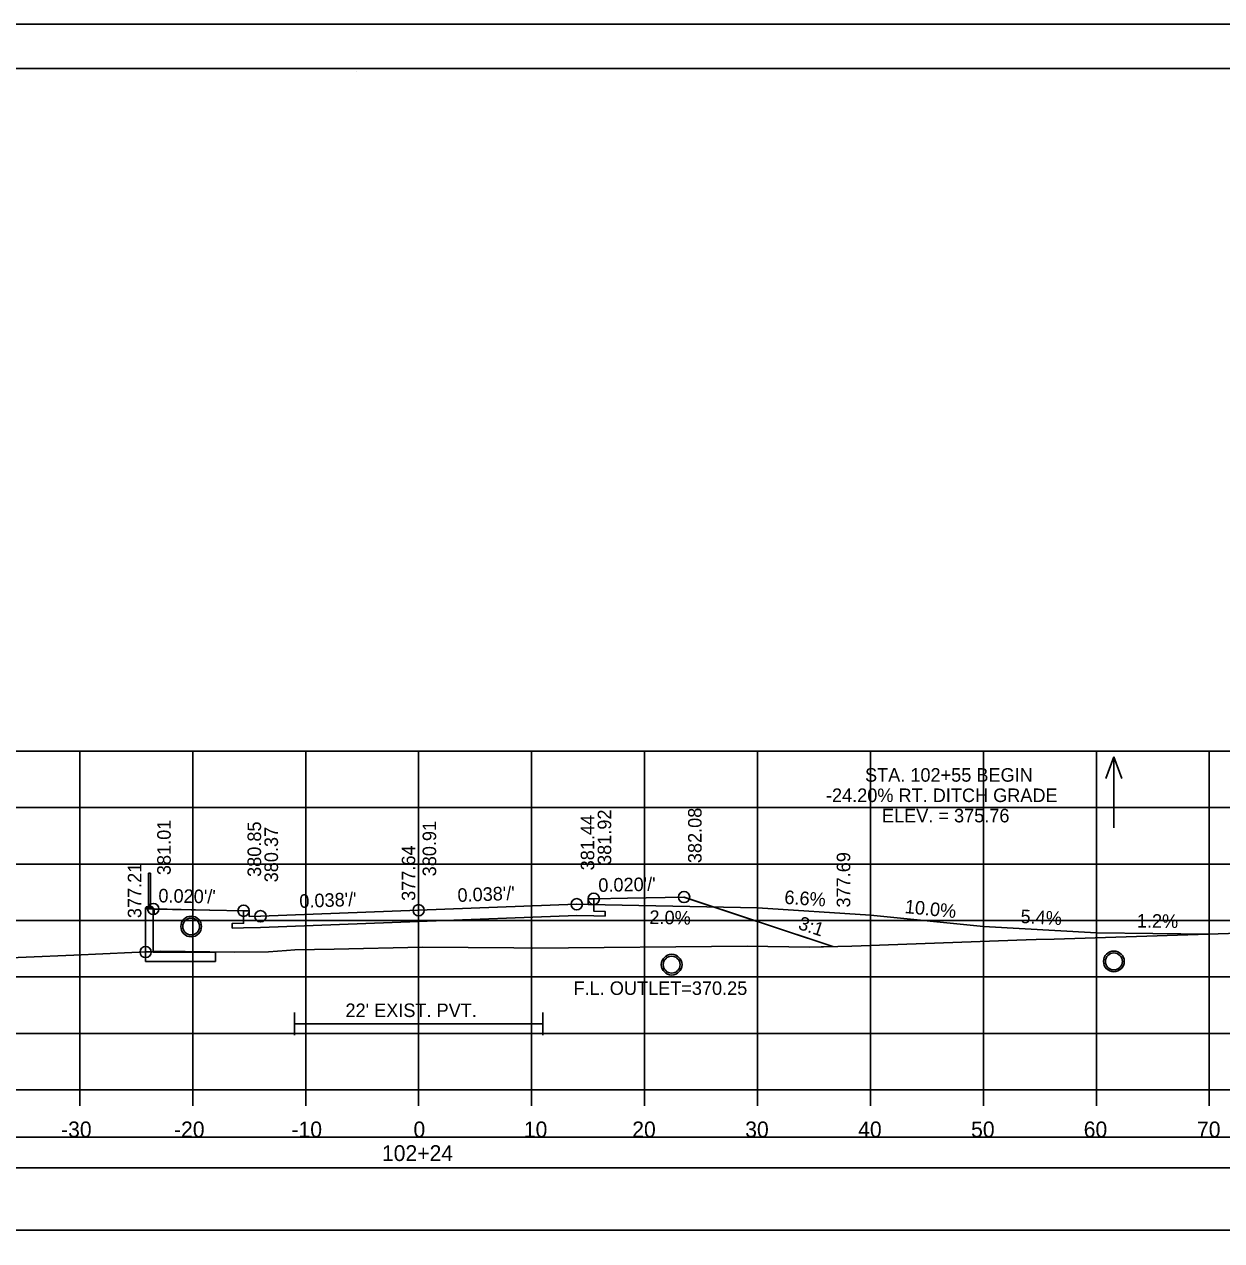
# Model space of a CAD drawing. Extents: x -37291014 to -37290680, y -936053 to -933067.
# Drawn here: x -37290878 to -37290772, y -935521 to -935413.3 of the extents above; entities that cross this region are included whole.
import ezdxf

# ---------------------------------------------------------------- set-up
doc = ezdxf.new("R2010")
doc.units = 0
for name, color, linetype in [('Default', 7, 'Continuous'), ('R_Alt Surface', 7, 'Continuous'), ('R_Axis', 7, 'Continuous'), ('R_Axis Annot', 7, 'Continuous'), ('R_Border', 7, 'Continuous'), ('R_Contours', 7, 'Continuous'), ('R_Drive', 7, 'Continuous'), ('R_Exist Surface', 7, 'Continuous'), ('R_Fin Surface', 7, 'Continuous'), ('R_Grid', 7, 'Continuous'), ('R_No Plot', 7, 'Continuous'), ('R_Water', 7, 'Continuous'), ('R_Water Annot', 7, 'Continuous'), ('R_Xsect Elev', 7, 'Continuous'), ('R_Xsect Slope', 7, 'Continuous')]:
    doc.layers.add(name, color=color, linetype=linetype)

msp = doc.modelspace()

# ---------------------------------------------------------------- linework, layer by layer
at = {"layer": 'Default'}
for p, q in [((-37290867.02, -935491.45), (-37290867.02, -935488.45)), ((-37290867.02, -935488.45), (-37290866.85, -935488.45)), ((-37290866.85, -935488.45), (-37290866.85, -935491.45)), ((-37290867.21, -935491.47), (-37290867.27, -935491.53)), ((-37290867.27, -935491.53), (-37290867.27, -935496.28)), ((-37290866.66, -935491.45), (-37290867.21, -935491.45)), ((-37290867.21, -935491.45), (-37290867.21, -935491.47)), ((-37290866.66, -935491.47), (-37290867.21, -935491.47)), ((-37290866.66, -935491.47), (-37290866.66, -935491.45)), ((-37290866.6, -935491.53), (-37290866.66, -935491.47)), ((-37290866.6, -935495.44), (-37290866.6, -935491.53)), ((-37290861.1, -935496.28), (-37290867.27, -935496.28)), ((-37290861.1, -935495.44), (-37290866.6, -935495.44)), ((-37290861.1, -935496.28), (-37290861.1, -935495.44))]:
    msp.add_line(p, q, dxfattribs=at)
msp.add_lwpolyline([(-37290866.52, -935492.13), (-37290866.6, -935492.13), (-37290866.6, -935491.63), (-37290866.52, -935491.63), (-37290866.52, -935492.13)], dxfattribs=at)
for points in [[(-37290992.48, -935514.55), (-37290693.72, -935514.55), (-37290693.72, -935511.85), (-37290992.48, -935511.85)], [(-37290992.48, -935520.08), (-37290693.72, -935520.08), (-37290693.72, -935514.55), (-37290992.48, -935514.55)]]:
    msp.add_lwpolyline(points, close=True, dxfattribs=at)
at = {"layer": 'R_Alt Surface'}
for points in [[(-37290827.6, -935490.73), (-37290827.6, -935491.82), (-37290826.59, -935491.84), (-37290826.6, -935492.26), (-37290827.6, -935492.24), (-37290829.1, -935492.21), (-37290843.1, -935492.74), (-37290857.1, -935493.27), (-37290858.6, -935493.3), (-37290859.6, -935493.32), (-37290859.61, -935492.91), (-37290858.6, -935492.89), (-37290858.6, -935491.79)], [(-37290854.1, -935500.8), (-37290854.1, -935502.8)], [(-37290832.1, -935500.8), (-37290832.1, -935502.8)], [(-37290854.1, -935501.8), (-37290832.1, -935501.8)]]:
    msp.add_lwpolyline(points, dxfattribs=at)
at = {"layer": 'R_Axis'}
for p, q in [((-37290993.1, -935507.65), (-37290693.1, -935507.65)), ((-37290873.1, -935509.05), (-37290873.1, -935507.65)), ((-37290863.1, -935509.05), (-37290863.1, -935507.65)), ((-37290853.1, -935509.05), (-37290853.1, -935507.65)), ((-37290843.1, -935509.05), (-37290843.1, -935507.65)), ((-37290833.1, -935509.05), (-37290833.1, -935507.65)), ((-37290823.1, -935509.05), (-37290823.1, -935507.65)), ((-37290813.1, -935509.05), (-37290813.1, -935507.65)), ((-37290803.1, -935509.05), (-37290803.1, -935507.65)), ((-37290793.1, -935509.05), (-37290793.1, -935507.65)), ((-37290783.1, -935509.05), (-37290783.1, -935507.65)), ((-37290773.1, -935509.05), (-37290773.1, -935507.65))]:
    msp.add_line(p, q, dxfattribs=at)
at = {"layer": 'R_Border'}
for p, q in [((-37291001.1, -935417.19), (-37290684.92, -935417.19)), ((-37290848.58, -935417.45), (-37290848.58, -935417.45)), ((-37290848.58, -935417.45), (-37290848.58, -935417.45))]:
    msp.add_line(p, q, dxfattribs=at)
at = {"layer": 'R_Contours'}
for p, q in [((-37290806.44, -935494.96), (-37290819.61, -935490.57)), ((-37290866.6, -935492.13), (-37290866.6, -935495.41)), ((-37290866.6, -935495.41), (-37290867.27, -935495.44)), ((-37290867.27, -935496.28), (-37290861.1, -935496.28)), ((-37290866.6, -935495.44), (-37290866.6, -935495.41)), ((-37290861.1, -935495.44), (-37290866.6, -935495.44)), ((-37290861.1, -935496.28), (-37290861.1, -935495.44))]:
    msp.add_line(p, q, dxfattribs=at)
for points in [[(-37290827.6, -935490.73), (-37290827.6, -935491.82), (-37290826.59, -935491.84), (-37290826.6, -935492.26), (-37290827.6, -935492.24), (-37290829.1, -935492.21), (-37290843.1, -935492.74), (-37290857.1, -935493.27), (-37290858.6, -935493.3), (-37290859.6, -935493.32), (-37290859.61, -935492.91), (-37290858.6, -935492.89), (-37290858.6, -935491.79)], [(-37290819.61, -935490.57), (-37290824.6, -935490.67), (-37290827.6, -935490.73)], [(-37290866.52, -935491.64), (-37290866.52, -935492.13), (-37290866.6, -935492.13)], [(-37290858.6, -935491.79), (-37290861.6, -935491.73), (-37290861.61, -935491.73), (-37290866.52, -935491.64)], [(-37290866.6, -935495.41), (-37290865.92, -935495.38), (-37290859.42, -935495.45), (-37290856.4, -935495.43), (-37290854.81, -935495.31), (-37290854.05, -935495.26), (-37290850.57, -935495.19), (-37290842.76, -935495), (-37290834.67, -935495.08), (-37290832.98, -935495.11), (-37290814.01, -935494.91), (-37290808.5, -935495), (-37290806.44, -935494.96)], [(-37290867.27, -935495.44), (-37290867.27, -935495.44), (-37290867.27, -935496.28)]]:
    msp.add_lwpolyline(points, dxfattribs=at)
at = {"layer": 'R_Drive'}
for p, q in [((-37290828.1, -935491.23), (-37290813.1, -935491.53)), ((-37290813.1, -935491.53), (-37290803.1, -935492.19)), ((-37290803.1, -935492.19), (-37290793.1, -935493.19)), ((-37290793.1, -935493.19), (-37290783.1, -935493.73)), ((-37290783.1, -935493.73), (-37290773.1, -935493.85))]:
    msp.add_line(p, q, dxfattribs=at)
at = {"layer": 'R_Exist Surface'}
msp.add_lwpolyline([(-37290882.1, -935496.08), (-37290873.62, -935495.73), (-37290865.92, -935495.38), (-37290859.42, -935495.45), (-37290856.4, -935495.43), (-37290854.81, -935495.31), (-37290854.05, -935495.26), (-37290850.57, -935495.19), (-37290842.76, -935495), (-37290834.67, -935495.08), (-37290832.98, -935495.11), (-37290814.01, -935494.91), (-37290808.5, -935495), (-37290804.76, -935494.92), (-37290789.31, -935494.37), (-37290788.44, -935494.34), (-37290786.85, -935494.29), (-37290774.08, -935493.88), (-37290760.71, -935493.46)], dxfattribs=at)
at = {"layer": 'R_Fin Surface'}
msp.add_line((-37290819.6, -935490.57), (-37290806.44, -935494.96), dxfattribs=at)
msp.add_lwpolyline([(-37290867.27, -935495.44), (-37290867.27, -935491.64), (-37290867.27, -935491.63), (-37290867.27, -935491.63), (-37290866.6, -935491.63), (-37290861.61, -935491.73), (-37290861.6, -935491.73), (-37290861.6, -935491.73), (-37290858.6, -935491.79), (-37290858.1, -935491.79), (-37290858.1, -935491.79), (-37290858.1, -935492.29), (-37290858.1, -935492.29), (-37290857.1, -935492.27), (-37290857.1, -935492.27), (-37290843.12, -935491.74), (-37290843.1, -935491.74), (-37290829.12, -935491.21), (-37290829.1, -935491.21), (-37290828.1, -935491.23), (-37290828.1, -935491.23), (-37290828.1, -935491.23), (-37290828.1, -935490.73), (-37290827.6, -935490.73), (-37290827.6, -935490.73), (-37290827.6, -935490.73), (-37290824.6, -935490.67), (-37290819.61, -935490.57), (-37290819.6, -935490.57)], dxfattribs=at)
at = {"layer": 'R_Grid'}
for p, q in [((-37290993.1, -935477.65), (-37290693.1, -935477.65)), ((-37290873.1, -935507.65), (-37290873.1, -935477.65)), ((-37290863.1, -935507.65), (-37290863.1, -935477.65)), ((-37290853.1, -935507.65), (-37290853.1, -935477.65)), ((-37290843.1, -935507.65), (-37290843.1, -935477.65)), ((-37290833.1, -935507.65), (-37290833.1, -935477.65)), ((-37290823.1, -935507.65), (-37290823.1, -935477.65)), ((-37290813.1, -935507.65), (-37290813.1, -935477.65)), ((-37290803.1, -935507.65), (-37290803.1, -935477.65)), ((-37290793.1, -935507.65), (-37290793.1, -935477.65)), ((-37290783.1, -935507.65), (-37290783.1, -935477.65)), ((-37290773.1, -935507.65), (-37290773.1, -935477.65)), ((-37290993.1, -935482.65), (-37290693.1, -935482.65)), ((-37290993.1, -935487.65), (-37290693.1, -935487.65)), ((-37290993.1, -935492.65), (-37290693.1, -935492.65)), ((-37290993.1, -935497.65), (-37290693.1, -935497.65)), ((-37290993.1, -935502.65), (-37290693.1, -935502.65)), ((-37290993.1, -935507.65), (-37290693.1, -935507.65))]:
    msp.add_line(p, q, dxfattribs=at)
at = {"layer": 'R_No Plot'}
msp.add_line((-37291013.5, -935413.29), (-37290680.17, -935413.29), dxfattribs=at)
for points in [[(-37291013.51, -935413.29), (-37290680.17, -935413.29), (-37290680.17, -935626.63), (-37291013.51, -935626.63)], [(-37290767.18, -935417.19), (-37290747.56, -935417.19), (-37290747.56, -935427.07), (-37290731.45, -935427.07), (-37290708.25, -935427.07), (-37290708.25, -935451.4), (-37290684.92, -935451.4), (-37290684.92, -935622.65), (-37291001.1, -935622.65), (-37291001.1, -935417.19)]]:
    msp.add_lwpolyline(points, close=True, dxfattribs=at)
for centre, radius in [((-37290829.1, -935491.21), 0.5), ((-37290829.1, -935491.21), 0.5), ((-37290827.6, -935490.73), 0.5), ((-37290819.6, -935490.57), 0.5), ((-37290866.6, -935491.63), 0.5), ((-37290858.6, -935491.79), 0.5), ((-37290857.1, -935492.27), 0.5), ((-37290843.1, -935491.74), 0.5), ((-37290863.24, -935493.18), 0.917), ((-37290867.27, -935495.44), 0.5), ((-37290820.7, -935496.56), 0.917), ((-37290781.55, -935496.27), 0.917)]:
    msp.add_circle(centre, radius, dxfattribs=at)
at = {"layer": 'R_Water'}
for centre in [(-37290863.24, -935493.18), (-37290820.7, -935496.56), (-37290781.55, -935496.27)]:
    msp.add_circle(centre, 0.75, dxfattribs=at)
at = {"layer": 'R_Water Annot'}
for p, q in [((-37290781.55, -935478.16), (-37290782.25, -935480.09)), ((-37290781.55, -935484.45), (-37290781.55, -935478.16)), ((-37290781.55, -935478.16), (-37290780.85, -935480.09))]:
    msp.add_line(p, q, dxfattribs=at)
at = {"layer": 'R_Xsect Elev'}
msp.add_line((-37290843.1, -935495), (-37290843.1, -935483.91), dxfattribs=at)

# ---------------------------------------------------------------- texts
at = {"layer": 'R_Axis Annot'}
for s, p in [('-30', (-37290874.76, -935511.85)), ('-20', (-37290864.76, -935511.85)), ('-10', (-37290854.36, -935511.85)), ('0', (-37290843.56, -935511.85)), ('10', (-37290833.79, -935511.85)), ('20', (-37290824.19, -935511.85)), ('30', (-37290814.19, -935511.85)), ('40', (-37290804.19, -935511.85)), ('50', (-37290794.19, -935511.85)), ('60', (-37290784.22, -935511.85)), ('70', (-37290774.19, -935511.85)), ('102+24', (-37290846.35, -935513.95))]:
    msp.add_text(s, height=1.4, dxfattribs=at).set_placement(p)
at = {"layer": 'R_Water'}
msp.add_text("22' EXIST. PVT.", height=1.2, dxfattribs=at).set_placement((-37290849.58, -935501.2))
at = {"layer": 'R_Water Annot'}
msp.add_text('F.L. OUTLET=370.25', height=1.2, dxfattribs=at).set_placement((-37290829.39, -935499.24))
at = {"layer": 'R_Xsect Elev'}
for s, p in [('STA. 102+55 BEGIN ', (-37290803.58, -935480.36)), ('-24.20% RT. DITCH GRADE', (-37290807.04, -935482.16)), ('ELEV. = 375.76', (-37290802.08, -935483.96))]:
    msp.add_text(s, height=1.2, dxfattribs=at).set_placement(p)
for s, rotation, p in [('381.44', 90, (-37290827.55, -935488.21)), ('381.92', 90, (-37290826.05, -935487.73)), ('382.08', 90, (-37290818.05, -935487.57)), ('381.01', 90, (-37290865.05, -935488.63)), ('380.85', 90, (-37290857.05, -935488.79)), ('380.37', 90, (-37290855.55, -935489.27)), ('380.91', 90, (-37290841.55, -935488.74)), ('377.64', 90, (-37290843.4, -935490.91)), ('377.69', 90, (-37290804.89, -935491.5)), ('377.21', 90, (-37290867.65, -935492.44)), ('6.6%', 356.224, (-37290810.75, -935491.17)), ('10.0%', 354.2894, (-37290800.1, -935491.99)), ('2.0%', 358.8542, (-37290822.68, -935492.95)), ('5.4%', 356.909, (-37290789.84, -935492.87)), ('1.2%', 359.2981, (-37290779.52, -935493.27))]:
    msp.add_text(s, height=1.2, rotation=rotation, dxfattribs=at).set_placement(p)
at = {"layer": 'R_Xsect Slope'}
for s, rotation, p in [("0.020'/'", 1.1458, (-37290827.18, -935490.12)), ("0.020'/'", 358.8542, (-37290866.15, -935491.04)), ("0.038'/'", 2.1762, (-37290839.64, -935491.01)), ("0.038'/'", 2.1762, (-37290853.64, -935491.54)), ('3:1', 341.5668, (-37290809.58, -935493.38))]:
    msp.add_text(s, height=1.2, rotation=rotation, dxfattribs=at).set_placement(p)

doc.saveas('drawing.dxf')
